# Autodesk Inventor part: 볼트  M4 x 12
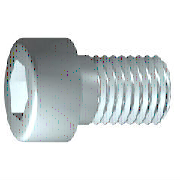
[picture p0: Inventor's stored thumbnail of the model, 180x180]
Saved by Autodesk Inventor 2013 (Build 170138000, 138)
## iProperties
IsCustomPart: 1
Created: 2012-02
Part Number: 볼트  M4 x 12
Material: 강철, 연강
Description: 6각 소켓 머리 캡 나사
Document SubType Name: Modeling
Standard: ISO 4762
Designer: mdu-01
Standard Revision: Fourth edition 2004-03-01
Standards Organization: ISO
Language: ko-KR
Size Designation: M4 x 12
Categories: <MemberInstance><Categories><Category DisplayName="조임쇠" InternalName="e4da775c-781d-43d5-af7c-5136215cf5a6" Mnemonic="FSTN"><Category DisplayName="볼트" InternalN
Density: 7.75 g/cm^3
Author: mdu-01
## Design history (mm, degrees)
sketch "스케치1"
  geometry: L1 (-1, 0)-(12, 0); L2 (12, 0)-(12, 2); L3 (12, 2)-(1.75, 2); L4 (1.75, 2)-(1.32, 2); L5 (1.32, 2)-(0, 2); L6 (0, 2)-(0, 3.5); L7 (0, 3.5)-(-4, 3.5); L8 (-4, 3.5)-(-4, 1.732); L9 (-4, 1.732)-(-2, 1.732); L10 (-2, 1.732)-(-1, 0); L11 (-7.2, 0)-(15.2, 0) reference; L12 (0, -0.7)-(0, 4.2) reference; L13 (1.75, 2)-(0, 2)
  constraints: 22 end point, 6 parallel, 2 collinear, 2 perpendicular, 1 horizontal, 1 point on line
  dimensions: "d1" = 10.25 distance from line of L3.end L2 (= GEL); "d2" = 0.42952 distance of L4.end L3.end (computed from GAL); "d3" = 4 distance between parallel lines of L8 L6 (= KOH); "d4" = 2 distance of L8.end L9.end (= INTI); "d5" = 60 deg angle of L10 L1; "d6" = 4 diameter of L3 L1 (= GD); "d7" = 4 diameter of L5 L1 (= BDM); "d8" = 3.4641 diameter of L9 L1 (= 1.1547 x SW); "d9" = 7 diameter of L7 L1 (= KOD); "d26" = 12 distance between parallel lines of L12 L2 (= NLG)
revolve "본체" sketch "스케치1" stored, may be unused: angle "d10" = 90 deg
sketch "스케치2"
  geometry: L1 (0, -4.9)-(0, 4.9) reference; L2 (-4.9, 0)-(4.9, 0) reference; L3 (1.732, 0)-(0.866, -1.5); L4 (0.866, -1.5)-(-0.866, -1.5); L5 (-0.866, -1.5)-(-1.732, 0); L6 (-1.732, 0)-(-0.866, 1.5); L7 (-0.866, 1.5)-(0.866, 1.5); L8 (0.866, 1.5)-(1.732, 0); 2 further points
  constraints: 12 end point, 1 coincident, 1 horizontal alignment, 1 point on line, 12 other
extrude "슬롯" join sketch "스케치2" stored distance "d11" = 10; taper "d12" = 0 deg
workplane "Work Plane1"
fillet "Fillet2" dims "d30" = 0.1 (= R)
body "Solid1"
fillet "모깎기1" dims "d17" = 0.4 (= RR)
feature "스레드" dims "d13" = 10.25 (= GEL), "d14" = 0
chamfer "모따기1" distance "d15" = 0.42941 (= -0.5 x SPD + 0.5 x GD); stored, may be unused: second distance "d16" = 0.42941 (= GUL), angle "d27" = 45 deg
other parameters: "GD" = 4 [user parameter; used in 2 equation terms], "NLG" = 12 [user parameter; used in 1 equation term], "GEL" = 10.25 [user parameter; used in 2 equation terms], "KOD" = 7 [user parameter; used in 1 equation term], "KOH" = 4 [user parameter; used in 1 equation term], "INTI" = 2 [user parameter; used in 1 equation term], "GAL" = 0.42941 (= 0.61345 x PTC) [user parameter; used in 1 equation term], "GUL" = 0.42941 (= 0.61345 x PTC) [user parameter; used in 1 equation term], "BDM" = 4 (= NND) [user parameter; used in 1 equation term], "SW" = 3 [user parameter; used in 2 equation terms], "RR" = 0.4 [user parameter; used in 1 equation term], "SPD" = 3.14117 (= NND - 1.2269 x PTC) [user parameter; used in 1 equation term], "d19" = 0, "d28" = 0, "d29" = 0, "R" = 0.1 [user parameter; used in 1 equation term], "TOA" = 30 deg [user parameter], "GD1" = 3.14117 (= THREADDIA - 1.2269 x PTC) [user parameter], "THREADDIA" = 4 [user parameter; used in 1 equation term], "FAWI" = 45 deg [user parameter], "TPU" = 14.28571 (computed from PTC) [user parameter], "PTC" = 0.7 [user parameter; used in 5 equation terms], "NND" = 4 [user parameter; used in 2 equation terms], "E0" = 3.465 (= 1.155 x SW) [user parameter]
